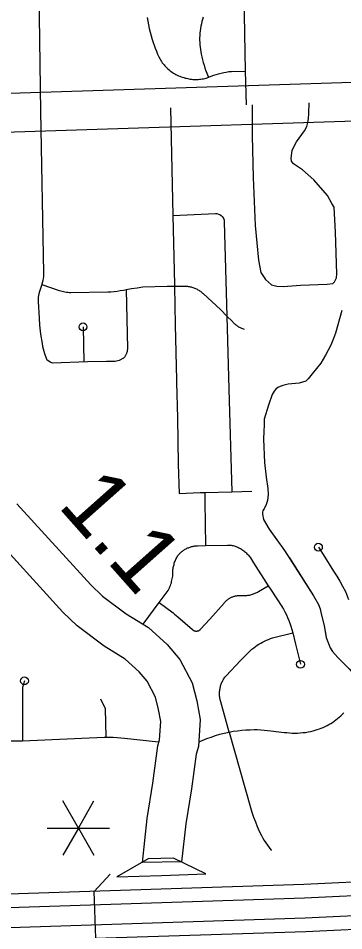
# Model space of a CAD drawing. Extents: x 309348 to 309445, y 336383 to 336484.
# Drawn here: x 309349.209 to 309349.625, y 336397.547 to 336398.714 of the extents above; entities that cross this region are included whole.
import ezdxf

# ---------------------------------------------------------------- set-up
doc = ezdxf.new("R2010")
doc.units = 0
doc.layers.add('R_Annotation', color=7, linetype='Continuous')

msp = doc.modelspace()

# ---------------------------------------------------------------- linework, layer by layer
at = {"layer": 'R_Annotation'}
for p, q in [((309349.2857, 336397.6786), (309349.2657, 336397.7133)), ((309349.2857, 336397.6786), (309349.3057, 336397.7133)), ((309349.2457, 336397.6786), (309349.2857, 336397.6786)), ((309349.2857, 336397.6786), (309349.2657, 336397.644)), ((309349.2857, 336397.6786), (309349.3257, 336397.6786)), ((309349.2857, 336397.6786), (309349.3057, 336397.644)), ((309349.3751, 336397.6391), (309349.335, 336397.6161)), ((309349.4075, 336397.6402), (309349.3751, 336397.6391)), ((309349.449, 336397.62), (309349.4075, 336397.6402)), ((309349.335, 336397.6161), (309349.392, 336397.6181)), ((309349.392, 336397.6181), (309349.449, 336397.62)), ((309349.308, 336397.5377), (309349.306, 336397.5977)), ((309349.307, 336397.5677), (309349.307, 336397.5677))]:
    msp.add_line(p, q, dxfattribs=at)
for points in [[(309349.2353, 336398.7475), (309349.2372, 336398.5948)], [(309349.4976, 336398.7429), (309349.4993, 336398.6463)], [(309349.3736, 336398.7151), (309349.3744, 336398.7103), (309349.3753, 336398.7056)], [(309349.4455, 336398.7154), (309349.4446, 336398.7126), (309349.4438, 336398.7097), (309349.4431, 336398.7068), (309349.4425, 336398.7039), (309349.442, 336398.7009), (309349.4416, 336398.698), (309349.4413, 336398.695), (309349.441, 336398.692), (309349.4409, 336398.689), (309349.4409, 336398.686), (309349.441, 336398.683), (309349.4412, 336398.6801), (309349.4415, 336398.6771), (309349.4419, 336398.6741), (309349.4424, 336398.6712), (309349.443, 336398.6682), (309349.4437, 336398.6646), (309349.4445, 336398.6609), (309349.4454, 336398.6573), (309349.4465, 336398.6538), (309349.4477, 336398.6502), (309349.449, 336398.6467), (309349.4523, 336398.6385)], [(309349.3753, 336398.7056), (309349.3763, 336398.7009), (309349.3775, 336398.6962), (309349.3789, 336398.6916), (309349.3803, 336398.687), (309349.3815, 336398.6832), (309349.3827, 336398.6794), (309349.3841, 336398.6756), (309349.3855, 336398.6719), (309349.3871, 336398.6682), (309349.3888, 336398.6645), (309349.3902, 336398.6617), (309349.3911, 336398.6601), (309349.3921, 336398.6586), (309349.3931, 336398.6572), (309349.3942, 336398.6557), (309349.3953, 336398.6544), (309349.3965, 336398.653), (309349.3977, 336398.6517), (309349.399, 336398.6504), (309349.4003, 336398.6492), (309349.4017, 336398.6481), (309349.4031, 336398.6469), (309349.4045, 336398.6459), (309349.406, 336398.6448), (309349.4075, 336398.6439), (309349.409, 336398.6429), (309349.4106, 336398.6421), (309349.4122, 336398.6413), (309349.4138, 336398.6405), (309349.4155, 336398.6398), (309349.4172, 336398.6392), (309349.4188, 336398.6386), (309349.4206, 336398.6381), (309349.4223, 336398.6376), (309349.4239, 336398.6372), (309349.4256, 336398.6368), (309349.4272, 336398.6365), (309349.4289, 336398.6362), (309349.4306, 336398.636), (309349.4323, 336398.6358), (309349.434, 336398.6357), (309349.4357, 336398.6357), (309349.4374, 336398.6357), (309349.4391, 336398.6358), (309349.4407, 336398.6359), (309349.4424, 336398.6361), (309349.4441, 336398.6364), (309349.4458, 336398.6367), (309349.4474, 336398.6371), (309349.4491, 336398.6375), (309349.4507, 336398.638), (309349.4523, 336398.6385)], [(309349.4523, 336398.6385), (309349.4527, 336398.6387), (309349.4558, 336398.64), (309349.4589, 336398.6411), (309349.4621, 336398.6422), (309349.4652, 336398.6431), (309349.4684, 336398.6439), (309349.4717, 336398.6446), (309349.4749, 336398.6452), (309349.4782, 336398.6457), (309349.4815, 336398.6461), (309349.4993, 336398.6463)], [(309349.4993, 336398.6463), (309349.5006, 336398.6031)], [(309348.9426, 336398.6094), (309348.9484, 336398.6095), (309348.9748, 336398.6118), (309349.0646, 336398.614), (309349.8623, 336398.6397)], [(309349.4035, 336398.5996), (309349.4065, 336398.4619)], [(309349.508, 336398.6034), (309349.508, 336398.5635), (309349.5095, 336398.5106), (309349.5121, 336398.4491), (309349.5162, 336398.4047), (309349.5191, 336398.3891), (309349.5254, 336398.3799), (309349.5328, 336398.3732), (309349.5395, 336398.3714), (309349.548, 336398.371), (309349.5702, 336398.3729), (309349.6043, 336398.374), (309349.6115, 336398.375), (309349.6136, 336398.3772), (309349.6159, 336398.3822), (309349.6165, 336398.3874), (309349.6146, 336398.4405), (309349.6129, 336398.4726), (309349.6102, 336398.477), (309349.6044, 336398.4872), (309349.5871, 336398.5076), (309349.5724, 336398.5203), (309349.5609, 336398.528), (309349.5586, 336398.5311), (309349.558, 336398.5352), (309349.5595, 336398.545), (309349.5613, 336398.5496), (309349.5649, 336398.5561), (309349.5751, 336398.57), (309349.578, 336398.5756), (309349.5792, 336398.5808), (309349.5801, 336398.5856), (309349.5807, 336398.5923), (309349.5809, 336398.6058)], [(309349.8382, 336398.589), (309349.1241, 336398.5659)], [(309349.2372, 336398.5948), (309349.2411, 336398.3886), (309349.2409, 336398.3837), (309349.2402, 336398.3787), (309349.2389, 336398.3738), (309349.2388, 336398.3734)], [(309349.4065, 336398.4619), (309349.4612, 336398.4643), (309349.4631, 336398.4642), (309349.4649, 336398.4637), (309349.4667, 336398.463), (309349.4683, 336398.4619), (309349.4697, 336398.4605), (309349.4709, 336398.459), (309349.4712, 336398.4583)], [(309349.4065, 336398.4619), (309349.4086, 336398.3736), (309349.4087, 336398.3714)], [(309349.4712, 336398.4583), (309349.4713, 336398.4582), (309349.4721, 336398.4559), (309349.4725, 336398.4535), (309349.4759, 336398.333)], [(309349.2388, 336398.3734), (309349.2376, 336398.3699), (309349.2359, 336398.3645), (309349.2351, 336398.3618), (309349.2344, 336398.3576), (309349.2342, 336398.3533), (309349.2343, 336398.3517), (309349.2354, 336398.3304), (309349.2361, 336398.3216), (309349.2374, 336398.3099), (309349.2392, 336398.2982), (309349.2399, 336398.2942), (309349.2405, 336398.2914), (309349.2422, 336398.2852), (309349.2445, 336398.2792), (309349.2454, 336398.2771)], [(309349.2388, 336398.3734), (309349.2613, 336398.3659), (309349.2631, 336398.3654), (309349.265, 336398.3649), (309349.2668, 336398.3645), (309349.2686, 336398.3642), (309349.2705, 336398.3639), (309349.2724, 336398.3637), (309349.2742, 336398.3635), (309349.2761, 336398.3635), (309349.3234, 336398.3642), (309349.3274, 336398.3644), (309349.3314, 336398.3647), (309349.3354, 336398.3652), (309349.3394, 336398.3658), (309349.3433, 336398.3665), (309349.3467, 336398.3672)], [(309349.3467, 336398.3672), (309349.3485, 336398.2916), (309349.3485, 336398.2909), (309349.3484, 336398.2903), (309349.3483, 336398.2897), (309349.3482, 336398.289), (309349.3481, 336398.2884), (309349.348, 336398.2877), (309349.3478, 336398.2871), (309349.3476, 336398.2865), (309349.3474, 336398.2859), (309349.3472, 336398.2852), (309349.3469, 336398.2846), (309349.3466, 336398.2841), (309349.3464, 336398.2835), (309349.346, 336398.2829), (309349.3457, 336398.2823), (309349.3454, 336398.2818), (309349.345, 336398.2813), (309349.3446, 336398.2807), (309349.3442, 336398.2802), (309349.3438, 336398.2797), (309349.3433, 336398.2793)], [(309349.3467, 336398.3672), (309349.3539, 336398.3684), (309349.3611, 336398.3695), (309349.3683, 336398.3704), (309349.3992, 336398.3713), (309349.4087, 336398.3714)], [(309349.4087, 336398.3714), (309349.4192, 336398.3715), (309349.4204, 336398.3715), (309349.4216, 336398.3716), (309349.4228, 336398.3715), (309349.424, 336398.3715), (309349.4252, 336398.3714), (309349.4264, 336398.3712), (309349.4275, 336398.371), (309349.4287, 336398.3708), (309349.4299, 336398.3705), (309349.4311, 336398.3702), (309349.4322, 336398.3699), (309349.4334, 336398.3695), (309349.4345, 336398.3691), (309349.4356, 336398.3686), (309349.4367, 336398.3681), (309349.4378, 336398.3675), (309349.4388, 336398.3669), (309349.4398, 336398.3663), (309349.4408, 336398.3657), (309349.4418, 336398.365), (309349.4428, 336398.3643), (309349.4437, 336398.3635), (309349.4446, 336398.3627), (309349.4455, 336398.3619), (309349.468, 336398.3414), (309349.4759, 336398.333)], [(309349.4087, 336398.3714), (309349.4098, 336398.3222), (309349.4112, 336398.2515), (309349.4113, 336398.2481)], [(309349.6229, 336398.3403), (309349.6148, 336398.3114), (309349.6122, 336398.3046), (309349.6089, 336398.296), (309349.6019, 336398.2833), (309349.5959, 336398.273), (309349.585, 336398.2592), (309349.5799, 336398.253), (309349.5766, 336398.2502), (309349.5727, 336398.2486), (309349.5683, 336398.2475), (309349.5541, 336398.2462), (309349.5473, 336398.2445), (309349.5438, 336398.2432), (309349.5411, 336398.2418), (309349.5385, 336398.2396), (309349.5363, 336398.2374), (309349.5337, 336398.2328), (309349.5291, 336398.2192), (309349.5236, 336398.2013), (309349.5234, 336398.1942), (309349.5232, 336398.1857), (309349.5225, 336398.176), (309349.524, 336398.1462), (309349.5262, 336398.1271), (309349.5282, 336398.1129), (309349.5287, 336398.105), (309349.5276, 336398.0973), (309349.526, 336398.0923), (309349.5236, 336398.0868), (309349.5219, 336398.0846), (309349.5214, 336398.082), (309349.5214, 336398.08)], [(309349.4759, 336398.333), (309349.4784, 336398.2399)], [(309349.4759, 336398.333), (309349.4826, 336398.3265), (309349.4833, 336398.3257), (309349.484, 336398.3249), (309349.4848, 336398.3242), (309349.4856, 336398.3234), (309349.4864, 336398.3227), (309349.4872, 336398.322), (309349.4881, 336398.3214), (309349.489, 336398.3208), (309349.4899, 336398.3202), (309349.4908, 336398.3196), (309349.4917, 336398.3191), (309349.4927, 336398.3186), (309349.4936, 336398.3181), (309349.4946, 336398.3177), (309349.4956, 336398.3173), (309349.4967, 336398.317), (309349.4977, 336398.3166), (309349.4978, 336398.3166)], [(309349.2917, 336398.3194), (309349.2928, 336398.2744)], [(309349.3433, 336398.2793), (309349.3381, 336398.2765), (309349.3328, 336398.2752), (309349.3218, 336398.275), (309349.2976, 336398.2745), (309349.2526, 336398.2732), (309349.2497, 336398.2742), (309349.2454, 336398.2771)], [(309349.4113, 336398.2481), (309349.4125, 336398.203), (309349.4134, 336398.144), (309349.4146, 336398.1065)], [(309349.4784, 336398.2399), (309349.482, 336398.1083)], [(309349.4146, 336398.1065), (309349.4415, 336398.1075), (309349.4475, 336398.1076)], [(309349.4475, 336398.1076), (309349.482, 336398.1083)], [(309349.4475, 336398.1076), (309349.4477, 336398.0963), (309349.4485, 336398.0398)], [(309349.482, 336398.1083), (309349.5075, 336398.1094)], [(309349.2071, 336398.093), (309349.3018, 336397.9895), (309349.3165, 336397.9753), (309349.347, 336397.9524), (309349.3756, 336397.9349), (309349.3995, 336397.9134), (309349.4156, 336397.8943), (309349.4312, 336397.8643), (309349.4374, 336397.8411), (309349.4414, 336397.8176), (309349.4393, 336397.7829), (309349.4364, 336397.7732), (309349.4303, 336397.7287), (309349.4234, 336397.684), (309349.4179, 336397.6353), (309349.3676, 336397.6348), (309349.3738, 336397.6907), (309349.3808, 336397.7359), (309349.3874, 336397.7837), (309349.3897, 336397.7915), (309349.3911, 336397.8149), (309349.3884, 336397.8304), (309349.3843, 336397.8461), (309349.3738, 336397.8663), (309349.3635, 336397.8785), (309349.3455, 336397.8947), (309349.3188, 336397.911), (309349.284, 336397.9372), (309349.2659, 336397.9547), (309349.1685, 336398.0611)], [(309349.5214, 336398.08), (309349.5227, 336398.0732), (309349.53, 336398.0607), (309349.5497, 336398.0337), (309349.5865, 336397.9754), (309349.5929, 336397.9644), (309349.5951, 336397.9591), (309349.5959, 336397.9548), (309349.6001, 336397.937), (309349.6029, 336397.9223), (309349.6078, 336397.9091), (309349.6108, 336397.9044), (309349.6176, 336397.8966), (309349.6323, 336397.8822)], [(309349.5214, 336398.08), (309349.5227, 336398.0732), (309349.53, 336398.0607), (309349.5407, 336398.046)], [(309349.4105, 336398.0222), (309349.411, 336398.0233), (309349.4116, 336398.0244), (309349.4122, 336398.0255), (309349.4128, 336398.0265), (309349.4135, 336398.0276), (309349.4142, 336398.0284), (309349.415, 336398.0292), (309349.4157, 336398.03), (309349.4165, 336398.0307), (309349.4173, 336398.0315), (309349.4181, 336398.0322), (309349.419, 336398.0328), (309349.4199, 336398.0335), (309349.4208, 336398.0341), (309349.4217, 336398.0347), (309349.4226, 336398.0352), (309349.4236, 336398.0358), (309349.4245, 336398.0363), (309349.4255, 336398.0367), (309349.4265, 336398.0371), (309349.4275, 336398.0375), (309349.4286, 336398.0379), (309349.4296, 336398.0382), (309349.4306, 336398.0385), (309349.4317, 336398.0387), (309349.4328, 336398.039), (309349.4338, 336398.0391), (309349.4349, 336398.0393), (309349.436, 336398.0394), (309349.4371, 336398.0395), (309349.4382, 336398.0395), (309349.4485, 336398.0398)], [(309349.4485, 336398.0398), (309349.4764, 336398.0405), (309349.4776, 336398.0405), (309349.4789, 336398.0404), (309349.4801, 336398.0403), (309349.4813, 336398.0402), (309349.4825, 336398.04), (309349.4837, 336398.0397), (309349.485, 336398.0394), (309349.4862, 336398.039), (309349.4874, 336398.0386), (309349.4886, 336398.0381), (309349.4897, 336398.0376), (309349.4909, 336398.0371), (309349.492, 336398.0365), (309349.4932, 336398.0359), (309349.4943, 336398.0352), (309349.4953, 336398.0345), (309349.4964, 336398.0338), (309349.4975, 336398.033), (309349.4985, 336398.0322), (309349.4996, 336398.0313), (309349.5006, 336398.0304), (309349.5015, 336398.0294), (309349.5025, 336398.0285), (309349.5034, 336398.0275), (309349.5043, 336398.0264), (309349.5051, 336398.0254), (309349.5059, 336398.0243), (309349.5098, 336398.0179), (309349.5288, 336397.9885)], [(309349.5929, 336398.0377), (309349.6012, 336398.0248), (309349.6123, 336398.0071), (309349.6163, 336398.0007), (309349.6202, 336397.9943), (309349.6239, 336397.9877), (309349.6274, 336397.981), (309349.6289, 336397.9776), (309349.6302, 336397.9742), (309349.6315, 336397.9707)], [(309349.5557, 336398.0242), (309349.5865, 336397.9754), (309349.5929, 336397.9644), (309349.5951, 336397.9591), (309349.5957, 336397.9561)], [(309349.3892, 336397.967), (309349.4007, 336397.9825), (309349.4015, 336397.9841), (309349.4023, 336397.9856), (309349.4029, 336397.9872), (309349.4036, 336397.9888), (309349.4041, 336397.9904), (309349.4047, 336397.9921), (309349.4051, 336397.9937), (309349.4055, 336397.9954), (309349.4059, 336397.9971), (309349.4062, 336397.9988), (309349.4064, 336398.0005), (309349.4066, 336398.0022), (309349.4067, 336398.0039), (309349.4068, 336398.0056), (309349.4068, 336398.0074), (309349.4068, 336398.0091), (309349.407, 336398.0104), (309349.4072, 336398.0118), (309349.4074, 336398.0131), (309349.4078, 336398.0145), (309349.4081, 336398.0158), (309349.4085, 336398.0171), (309349.4089, 336398.0184), (309349.4094, 336398.0197), (309349.4099, 336398.021), (309349.4105, 336398.0222)], [(309349.4371, 336397.9305), (309349.4374, 336397.9305), (309349.4376, 336397.9305), (309349.4379, 336397.9305), (309349.4381, 336397.9306), (309349.4384, 336397.9306), (309349.4386, 336397.9307), (309349.4389, 336397.9308), (309349.4391, 336397.9308), (309349.4393, 336397.9309), (309349.4396, 336397.931), (309349.4398, 336397.9311), (309349.44, 336397.9312), (309349.4402, 336397.9313), (309349.4405, 336397.9315), (309349.4407, 336397.9316), (309349.4409, 336397.9317), (309349.4411, 336397.9319), (309349.4413, 336397.932), (309349.4415, 336397.9322), (309349.4417, 336397.9323), (309349.4419, 336397.9325), (309349.442, 336397.9327), (309349.4422, 336397.9329), (309349.4539, 336397.9458), (309349.4721, 336397.9661), (309349.4727, 336397.9668), (309349.4732, 336397.9675), (309349.4738, 336397.9681), (309349.4745, 336397.9687), (309349.4751, 336397.9694), (309349.4758, 336397.9699), (309349.4765, 336397.9705), (309349.4772, 336397.971), (309349.4779, 336397.9715), (309349.4786, 336397.972), (309349.4794, 336397.9725), (309349.4801, 336397.9729), (309349.4809, 336397.9733), (309349.4817, 336397.9737), (309349.4825, 336397.9741), (309349.4833, 336397.9744), (309349.4842, 336397.9747), (309349.485, 336397.975), (309349.4859, 336397.9752), (309349.4867, 336397.9754), (309349.4876, 336397.9756), (309349.4885, 336397.9757), (309349.4893, 336397.9759), (309349.4902, 336397.9759), (309349.4911, 336397.976), (309349.492, 336397.976), (309349.4929, 336397.976), (309349.4937, 336397.976), (309349.4946, 336397.9759), (309349.4955, 336397.9758), (309349.4967, 336397.9758), (309349.4979, 336397.9758), (309349.4991, 336397.9758), (309349.5003, 336397.9759), (309349.5015, 336397.976), (309349.5027, 336397.9762), (309349.5039, 336397.9764), (309349.5051, 336397.9766), (309349.5062, 336397.9769), (309349.5074, 336397.9772), (309349.5085, 336397.9775), (309349.5097, 336397.9779), (309349.5108, 336397.9784), (309349.5119, 336397.9788), (309349.513, 336397.9793), (309349.5141, 336397.9799), (309349.5151, 336397.9804), (309349.5162, 336397.981), (309349.5288, 336397.9885)], [(309349.5288, 336397.9885), (309349.5326, 336397.9827), (309349.5462, 336397.9618), (309349.5482, 336397.9584), (309349.5501, 336397.9549), (309349.5519, 336397.9514), (309349.5535, 336397.9478), (309349.5551, 336397.9442), (309349.5565, 336397.9405), (309349.5577, 336397.9368), (309349.56, 336397.9283)], [(309349.3688, 336397.9391), (309349.3892, 336397.967)], [(309349.3892, 336397.967), (309349.4069, 336397.9536), (309349.4089, 336397.9521), (309349.4109, 336397.9505), (309349.4128, 336397.9488), (309349.4318, 336397.9323), (309349.432, 336397.9321), (309349.4322, 336397.932), (309349.4324, 336397.9318), (309349.4326, 336397.9317), (309349.4328, 336397.9315), (309349.433, 336397.9314), (309349.4333, 336397.9313), (309349.4335, 336397.9312), (309349.4337, 336397.9311), (309349.434, 336397.931), (309349.4342, 336397.9309), (309349.4344, 336397.9308), (309349.4347, 336397.9307), (309349.4349, 336397.9307), (309349.4351, 336397.9306), (309349.4354, 336397.9306), (309349.4356, 336397.9305), (309349.4359, 336397.9305), (309349.4361, 336397.9305), (309349.4364, 336397.9304), (309349.4366, 336397.9304), (309349.4369, 336397.9304), (309349.4371, 336397.9305)], [(309349.6014, 336397.9303), (309349.6029, 336397.9223), (309349.6078, 336397.9091), (309349.6108, 336397.9044), (309349.6176, 336397.8966), (309349.6323, 336397.8822), (309349.6433, 336397.8692), (309349.6447, 336397.8676), (309349.6455, 336397.8666)], [(309349.4787, 336397.8013), (309349.4679, 336397.84), (309349.4675, 336397.8412), (309349.4672, 336397.8424), (309349.467, 336397.8436), (309349.4668, 336397.8448), (309349.4666, 336397.846), (309349.4665, 336397.8472), (309349.4664, 336397.8484), (309349.4664, 336397.8496), (309349.4664, 336397.8509), (309349.4664, 336397.8521), (309349.4665, 336397.8533), (309349.4666, 336397.8545), (309349.4668, 336397.8557), (309349.467, 336397.8569), (309349.4672, 336397.8581), (309349.4675, 336397.8593), (309349.4678, 336397.8605), (309349.4682, 336397.8617), (309349.4686, 336397.8628), (309349.469, 336397.8639), (309349.4695, 336397.8651), (309349.47, 336397.8662), (309349.4706, 336397.8673), (309349.4712, 336397.8683), (309349.4718, 336397.8694), (309349.4725, 336397.8704), (309349.4732, 336397.8714), (309349.4739, 336397.8724), (309349.4747, 336397.8733), (309349.4932, 336397.8927), (309349.5079, 336397.9074), (309349.5101, 336397.9091), (309349.5122, 336397.9107), (309349.5145, 336397.9123), (309349.5168, 336397.9137), (309349.5191, 336397.9151), (309349.5215, 336397.9165), (309349.5239, 336397.9177), (309349.5264, 336397.9188), (309349.5289, 336397.9199), (309349.5314, 336397.9209), (309349.534, 336397.9217), (309349.56, 336397.9283)], [(309349.56, 336397.9283), (309349.5637, 336397.9136), (309349.5699, 336397.888)], [(309349.2167, 336397.8668), (309349.214, 336397.8583), (309349.2142, 336397.79)], [(309349.314, 336397.8437), (309349.3201, 336397.8316), (309349.3208, 336397.7949)], [(309349.4787, 336397.8013), (309349.484, 336397.8023), (309349.4893, 336397.8031), (309349.4947, 336397.8037), (309349.5, 336397.8042), (309349.5054, 336397.8044), (309349.5108, 336397.8046), (309349.5148, 336397.8046), (309349.5319, 336397.8031), (309349.5491, 336397.801), (309349.5524, 336397.8006), (309349.5558, 336397.8003), (309349.5592, 336397.8001), (309349.5627, 336397.8001), (309349.5661, 336397.8001), (309349.5695, 336397.8003), (309349.5729, 336397.8006), (309349.5763, 336397.801), (309349.5796, 336397.8016), (309349.583, 336397.8022), (309349.5863, 336397.803), (309349.5889, 336397.8037), (309349.5915, 336397.8045), (309349.5941, 336397.8054), (309349.5966, 336397.8063), (309349.5991, 336397.8074), (309349.6015, 336397.8085), (309349.604, 336397.8097), (309349.6063, 336397.811), (309349.6087, 336397.8124), (309349.611, 336397.8138), (309349.6132, 336397.8153), (309349.6154, 336397.8169), (309349.6175, 336397.8186), (309349.6196, 336397.8203), (309349.6216, 336397.8221), (309349.6235, 336397.824), (309349.6254, 336397.826)], [(309349.1848, 336397.7903), (309349.1858, 336397.7902), (309349.1868, 336397.7901), (309349.1879, 336397.7901), (309349.2142, 336397.79)], [(309349.2142, 336397.79), (309349.3186, 336397.7949), (309349.3208, 336397.7949)], [(309349.3208, 336397.7949), (309349.3263, 336397.7949), (309349.3304, 336397.7948), (309349.3352, 336397.7945), (309349.34, 336397.7941), (309349.3447, 336397.7936), (309349.3881, 336397.7889)], [(309349.4412, 336397.7893), (309349.4502, 336397.793), (309349.4556, 336397.795), (309349.4611, 336397.7968), (309349.4666, 336397.7985), (309349.4722, 336397.7999), (309349.4787, 336397.8013)], [(309349.4787, 336397.8013), (309349.506, 336397.7051), (309349.5079, 336397.6989), (309349.51, 336397.6927), (309349.5122, 336397.6867), (309349.5146, 336397.6807), (309349.5173, 336397.6748), (309349.5201, 336397.669), (309349.5218, 336397.6658), (309349.5237, 336397.6627), (309349.5257, 336397.6597), (309349.5278, 336397.6567), (309349.5299, 336397.6539), (309349.5322, 336397.651), (309349.5327, 336397.6505)], [(309352.6868, 336397.729), (309352.1859, 336397.7061), (309351.1163, 336397.6639), (309350.5792, 336397.645), (309349.6821, 336397.6116), (309349.5744, 336397.6063), (309349.1696, 336397.5933), (309349.0937, 336397.5896), (309348.838, 336397.5802), (309348.6889, 336397.576), (309348.5061, 336397.574), (309348.4455, 336397.5778), (309348.4023, 336397.5837), (309348.3471, 336397.5936), (309348.2597, 336397.6131), (309348.2175, 336397.6264), (309348.1904, 336397.6364), (309348.1261, 336397.6629)], [(309348.1138, 336397.6496), (309348.1842, 336397.6206), (309348.212, 336397.6103), (309348.2553, 336397.5967), (309348.3438, 336397.5769), (309348.3996, 336397.567), (309348.4438, 336397.5608), (309348.5057, 336397.557), (309348.6892, 336397.559), (309348.8386, 336397.5632), (309349.0944, 336397.5726), (309349.1703, 336397.5763), (309349.5751, 336397.5893), (309349.6829, 336397.5946), (309350.5798, 336397.6281), (309351.1169, 336397.6469), (309352.1866, 336397.6891), (309352.6878, 336397.712)], [(309352.6892, 336397.6861), (309352.1877, 336397.6631), (309351.1179, 336397.6209), (309350.5807, 336397.6021), (309349.684, 336397.5686), (309349.5761, 336397.5633), (309349.1714, 336397.5504), (309349.0955, 336397.5466), (309348.8394, 336397.5372), (309348.6897, 336397.533), (309348.505, 336397.5309), (309348.4412, 336397.5349), (309348.3955, 336397.5413), (309348.3387, 336397.5514), (309348.2486, 336397.5715), (309348.2036, 336397.5857), (309348.1748, 336397.5963), (309348.0954, 336397.6291)], [(309348.0833, 336397.616), (309348.0912, 336397.6124), (309348.1686, 336397.5805), (309348.1981, 336397.5696), (309348.2442, 336397.5551), (309348.3353, 336397.5348), (309348.3929, 336397.5245), (309348.4395, 336397.518), (309348.5046, 336397.5139), (309348.69, 336397.516), (309348.8399, 336397.5202), (309349.0962, 336397.5296), (309349.1721, 336397.5334), (309349.5768, 336397.5463), (309349.6847, 336397.5516), (309350.5813, 336397.5851), (309351.1185, 336397.604), (309352.1884, 336397.6461), (309352.6902, 336397.6691)], [(309349.3266, 336397.6196), (309349.306, 336397.5977)]]:
    msp.add_lwpolyline(points, dxfattribs=at)
for centre in [(309349.2917, 336398.3194), (309349.5929, 336398.0377), (309349.5699, 336397.888), (309349.2167, 336397.8668)]:
    msp.add_circle(centre, 0.005, dxfattribs=at)

# ---------------------------------------------------------------- texts
msp.add_text('1.1', height=0.08451, rotation=311.5646, dxfattribs=at).set_placement((309349.2581, 336398.0906))

doc.saveas('drawing.dxf')
